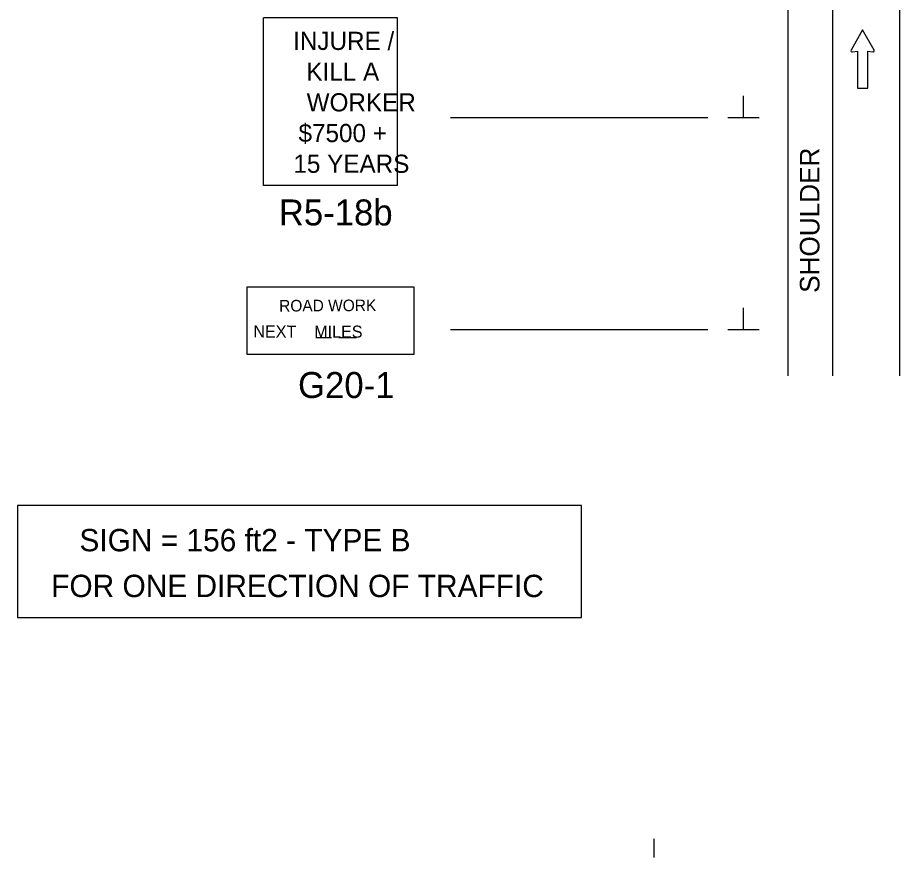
# Model space of a CAD drawing. Extents: x 19023 to 20762, y 4888 to 6104.
# Drawn here: x 19023 to 19338.9, y 5088.6 to 5389.3 of the extents above; entities that cross this region are included whole.
import ezdxf

# ---------------------------------------------------------------- set-up
doc = ezdxf.new("R2010")
doc.units = 0
for name, color, linetype in [('BORDER', 7, 'Continuous'), ('MT_SCRATCH_LEVEL_E', 7, 'Continuous'), ('PAVT_EDGE_EX', 7, 'Continuous'), ('TRAFFIC_SIGNS_PR', 7, 'Continuous'), ('TYPICAL_TEXT_DIMEN_PR', 7, 'Continuous')]:
    doc.layers.add(name, color=color, linetype=linetype)

msp = doc.modelspace()

# ---------------------------------------------------------------- linework, layer by layer
at = {"layer": 'BORDER'}
msp.add_line((19251.086, 5088.624), (19251.086, 5095.239), dxfattribs=at)
at = {"layer": 'MT_SCRATCH_LEVEL_E'}
for p, q in [((19325.723, 5384.986), (19321.612, 5377.745)), ((19325.723, 5384.986), (19321.612, 5377.745)), ((19329.87, 5377.745), (19325.723, 5384.986)), ((19329.87, 5377.745), (19325.723, 5384.986)), ((19322.094, 5377.061), (19323.871, 5377.377)), ((19322.094, 5377.061), (19323.871, 5377.377)), ((19323.871, 5377.377), (19323.871, 5364.119)), ((19323.871, 5377.377), (19323.871, 5364.119)), ((19327.613, 5364.119), (19327.613, 5377.377)), ((19327.613, 5377.377), (19329.39, 5377.061)), ((19327.613, 5364.119), (19327.613, 5377.377)), ((19327.613, 5377.377), (19329.39, 5377.061)), ((19323.871, 5364.119), (19327.613, 5364.119)), ((19323.871, 5364.119), (19327.613, 5364.119))]:
    msp.add_line(p, q, dxfattribs=at)
for centre, start, end in [((19322.02, 5377.521), 150.42484, 279.96381), ((19322.02, 5377.521), 150.42484, 279.96381), ((19329.46, 5377.522), 260.03619, 29.77312), ((19329.46, 5377.522), 260.03619, 29.77312)]:
    msp.add_arc(centre, 0.463, start, end, dxfattribs=at)
at = {"layer": 'PAVT_EDGE_EX'}
for p, q in [((19298.917, 6104.026), (19298.917, 5261.047)), ((19314.917, 6104.026), (19314.917, 5261.047)), ((19338.917, 6014.455), (19338.917, 5261.047))]:
    msp.add_line(p, q, dxfattribs=at)
msp.add_lwpolyline([(19338.917, 5314.455), (19338.917, 5289.455)], dxfattribs=at)
at = {"layer": 'TRAFFIC_SIGNS_PR'}
for p, q in [((19111.123, 5329.217), (19111.123, 5389.217)), ((19159.123, 5389.217), (19111.123, 5389.217)), ((19159.123, 5329.217), (19159.123, 5389.217)), ((19159.123, 5329.217), (19111.123, 5329.217))]:
    msp.add_line(p, q, dxfattribs=at)
at = {"layer": 'TYPICAL_TEXT_DIMEN_PR'}
for p, q in [((19283.073, 5353.576), (19283.073, 5361.361)), ((19270.246, 5353.414), (19178.112, 5353.414)), ((19277.448, 5353.576), (19283.073, 5353.576)), ((19283.073, 5353.576), (19288.698, 5353.576)), ((19283.073, 5277.659), (19283.073, 5285.444)), ((19270.246, 5277.497), (19178.112, 5277.497)), ((19277.448, 5277.659), (19283.073, 5277.659)), ((19283.073, 5277.659), (19288.698, 5277.659)), ((19135.521, 5274.66), (19129.819, 5274.66)), ((19144.462, 5274.66), (19138.113, 5274.66))]:
    msp.add_line(p, q, dxfattribs=at)
for points in [[(19105.123, 5268.844), (19165.123, 5268.844), (19165.123, 5292.844), (19105.123, 5292.844)], [(19023.032, 5174.541), (19225.027, 5174.541), (19225.027, 5214.686), (19023.032, 5214.686)]]:
    msp.add_lwpolyline(points, close=True, dxfattribs=at)

# ---------------------------------------------------------------- texts
at = {"layer": 'TRAFFIC_SIGNS_PR'}
for s, height, p in [('INJURE /', 6.5, (19121.729, 5377.764)), ('KILL A', 6.5, (19126.479, 5366.764)), ('WORKER', 6.5, (19126.574, 5355.764)), ('$7500 +', 6.5, (19123.666, 5344.765)), ('15 YEARS', 6.5, (19121.829, 5333.765)), ('R5-18b', 9.3, (19116.593, 5314.917)), ('G20-1', 9.3, (19123.488, 5253.121))]:
    msp.add_text(s, height=height, dxfattribs=at).set_placement(p)
at = {"layer": 'TYPICAL_TEXT_DIMEN_PR'}
for s, height, rotation, p in [('SHOULDER', 7, 90, (19310.279, 5290.774)), ('ROAD WORK', 4.145, 0.30058, (19116.726, 5284.081)), ('NEXT    MILES', 4.31295, 359.90144, (19107.486, 5274.797))]:
    msp.add_text(s, height=height, rotation=rotation, dxfattribs=at).set_placement(p)
for s, p in [('SIGN = 156 ft2 - TYPE B', (19045.17, 5198.227)), ('FOR ONE DIRECTION OF TRAFFIC', (19035.047, 5181.829))]:
    msp.add_text(s, height=8, dxfattribs=at).set_placement(p)

doc.saveas('drawing.dxf')
